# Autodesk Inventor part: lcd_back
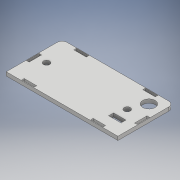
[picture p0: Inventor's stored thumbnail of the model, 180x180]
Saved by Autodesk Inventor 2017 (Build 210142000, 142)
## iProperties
Created: 2016-11
Part Number: lcd_back
Material: Generic
Document SubType Name: Modeling
Designer: mivas
Density: 1 g/cm^3
Appearance: Default
Author: mivas
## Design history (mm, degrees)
sketch "Sketch1"
  geometry: L1 (0, 0)-(90, 0); L2 (90, 0)-(90, 45); L3 (90, 45)-(0, 45); L4 (0, 45)-(0, 0)
  constraints: 8 end point, 2 parallel, 1 horizontal, 1 perpendicular
  dimensions: "d0" = 90 distance of L2.end L3.end; "d1" = 45 distance of L1.end L2.end
extrude "Extrusion1" new body sketch "Sketch1" distance "d2" = 3; taper "d3" = 0 deg
fillet "Fillet1" dims "d4" = 4
fillet "Fillet2" dims "d5" = 4
sketch "Sketch2"
  geometry: L1 (-89.5, 25.922)-(-87.5, 25.922); L2 (-87.5, 25.922)-(-87.5, 15.922); L3 (-87.5, 15.922)-(-89.5, 15.922); L4 (-89.5, 15.922)-(-89.5, 25.922); L5 (0, 0)-(-90, 0) reference; L6 (-90, 0)-(-90, 41) reference; L7 (-2.5, 25.922)-(-0.5, 25.922); L8 (-2.5, 15.922)-(-2.5, 25.922); L9 (-0.5, 25.922)-(-0.5, 15.922); L10 (-0.5, 15.922)-(-2.5, 15.922); L11 (0, 41)-(0, 0) reference; L12 (-77.581, 2.5)-(-67.581, 2.5); L13 (-67.581, 2.5)-(-67.581, 0.5); L14 (-67.581, 0.5)-(-77.581, 0.5); L15 (-77.581, 0.5)-(-77.581, 2.5); L16 (-77.581, 44.5)-(-67.581, 44.5); L17 (-77.581, 42.5)-(-77.581, 44.5); L18 (-67.581, 42.5)-(-77.581, 42.5); L19 (-67.581, 44.5)-(-67.581, 42.5); L20 (-22.025, 2.5)-(-12.025, 2.5); L21 (-22.025, 0.5)-(-22.025, 2.5); L22 (-12.025, 0.5)-(-22.025, 0.5); L23 (-12.025, 2.5)-(-12.025, 0.5); L24 (-86, 45)-(-4, 45) reference; L25 (-12.025, 42.5)-(-22.025, 42.5); L26 (-22.025, 44.5)-(-12.025, 44.5); L27 (-22.025, 42.5)-(-22.025, 44.5); L28 (-12.025, 44.5)-(-12.025, 42.5)
  constraints: 48 end point, 12 parallel, 6 horizontal, 6 perpendicular
  dimensions: "d6" = 15.922 distance between parallel lines of L5 L3; "d7" = 10 distance between parallel lines of L3 L1; "d8" = 2 distance between parallel lines of L2 L4; "d9" = 0.5 distance between parallel lines of L6 L4; "d10" = 10 distance between parallel lines of L10 L7; "d11" = 2 distance between parallel lines of L9 L8; "d12" = 0.5 distance between parallel lines of L11 L9; "d13" = 15.922 distance between parallel lines of L5 L10; "d14" = 85 distance between parallel lines of L8 L2 (derived); "d15" = 2 distance between parallel lines of L14 L12; "d16" = 10 distance from line of L12.end L15; "d17" = 0.5 distance between parallel lines of L5 L14; "d18" = 12.419 distance between parallel lines of L6 L15; "d19" = 2 distance between parallel lines of L18 L16; "d20" = 10 distance from line of L16.end L17; "d21" = 2 distance between parallel lines of L22 L20; "d22" = 10 distance from line of L20.end L21; "d23" = 45.556 distance between parallel lines of L21 L13; "d24" = 0.5 distance between parallel lines of L5 L22; "d25" = 0.5 distance between parallel lines of L24 L16; "d26" = 12.419 distance from line of L6.end L17; "d27" = 2 distance between parallel lines of L25 L26; "d28" = 10 distance from line of L26.end L27; "d29" = 45.556 distance between parallel lines of L27 L19; "d30" = 0.5 distance between parallel lines of L24 L26
extrude "Extrusion2" cut sketch "Sketch2" distance "d31" = 5; taper "d32" = 0 deg
sketch "Sketch3"
  geometry: L1 (-86, 45)-(-4, 45) reference; L2 (-90, 0)-(-90, 41) reference; L3 (-82, 14.5)-(-72, 14.5); L4 (-72, 14.5)-(-72, 10.5); L5 (-72, 10.5)-(-82, 10.5); L6 (-82, 10.5)-(-82, 14.5); L7 (0, 0)-(-90, 0) reference; L8 (0, 41)-(0, 0) reference; C1 r 5 at (-80, 35); C2 r 2.5 at (-10, 22.5); C3 r 2.5 at (-75, 22.5)
  constraints: 8 end point, 3 centre point, 2 parallel, 1 horizontal, 1 perpendicular
  dimensions: "d33" = 9.99994 diameter of C1; "d34" = 10 distance from line of C1.centre L1; "d35" = 10 distance from line of L2 C1.centre; "d36" = 10 distance between parallel lines of L4 L6; "d37" = 4 distance between parallel lines of L5 L3; "d38" = 10.5 distance between parallel lines of L7 L5; "d39" = 8 distance between parallel lines of L2 L6; "d40" = 5 diameter of C2; "d41" = 10 distance from line of L8 C2.centre; "d42" = 22.5 distance from line of L7 C2.centre; "d43" = 5 diameter of C3; "d44" = 60.00003 dimension on C2 C3; "d45" = 22.5 distance from line of L7 C3.centre
extrude "Extrusion3" cut sketch "Sketch3" distance "d46" = 5; taper "d47" = 0 deg
body "Solid1"
